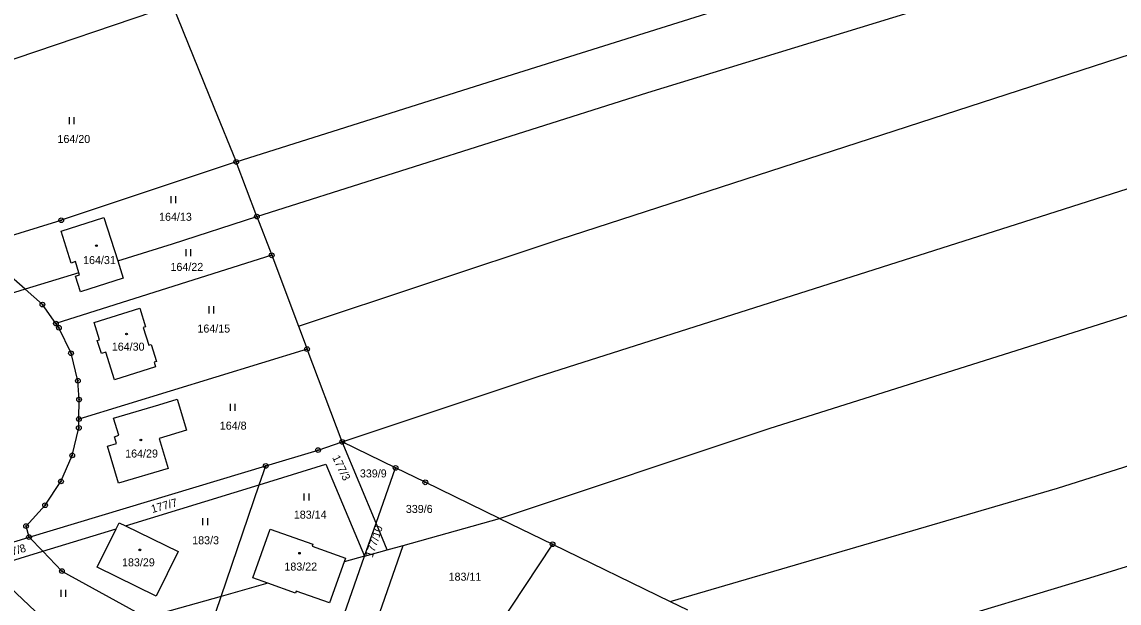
# Model space of a CAD drawing. Extents: x -762263 to -760336, y -1154405 to -1152076.
# Drawn here: x -761336.3 to -761103.3, y -1152463.4 to -1152340 of the extents above; entities that cross this region are included whole.
import ezdxf

# ---------------------------------------------------------------- set-up
doc = ezdxf.new("R2010")
doc.units = 0
for name, color, linetype in [('Vrstva 1', 7, 'Continuous'), ('Vrstva 18', 7, 'Continuous'), ('Vrstva 19', 7, 'Continuous'), ('Vrstva 24', 7, 'Continuous'), ('Vrstva 25', 7, 'Continuous'), ('Vrstva 6', 7, 'Continuous')]:
    doc.layers.add(name, color=color, linetype=linetype)

msp = doc.modelspace()

# ---------------------------------------------------------------- linework, layer by layer
at = {"layer": 'Vrstva 1'}
for p, q in [((-761375.09, -1152360.47), (-761304.35, -1152336.41)), ((-761304.35, -1152336.41), (-761295.51, -1152358.08)), ((-761295.51, -1152358.08), (-761290.77, -1152369.71)), ((-761290.77, -1152369.71), (-761327.94, -1152382.1)), ((-761286.38, -1152381.32), (-761290.77, -1152369.71)), ((-761348.02, -1152388.29), (-761327.94, -1152382.1)), ((-761327.95, -1152384.4), (-761318.87, -1152381.51)), ((-761318.87, -1152381.51), (-761315.96, -1152390.72)), ((-761304.29, -1152387.14), (-761286.38, -1152381.32)), ((-761286.38, -1152381.32), (-761283.26, -1152389.55)), ((-761325.83, -1152391.19), (-761327.95, -1152384.4)), ((-761315.96, -1152390.72), (-761304.29, -1152387.14)), ((-761283.26, -1152389.55), (-761329.07, -1152404.03)), ((-761324.89, -1152390.89), (-761325.83, -1152391.19)), ((-761324.18, -1152393.25), (-761324.89, -1152390.89)), ((-761315.96, -1152390.72), (-761314.79, -1152394.42)), ((-761283.26, -1152389.55), (-761277.56, -1152404.6)), ((-761335.62, -1152396.76), (-761339.78, -1152393.07)), ((-761324.18, -1152393.25), (-761335.62, -1152396.76)), ((-761324.94, -1152394), (-761324.04, -1152393.72)), ((-761324.04, -1152393.72), (-761324.18, -1152393.25)), ((-761323.88, -1152397.3), (-761324.94, -1152394)), ((-761314.79, -1152394.42), (-761323.88, -1152397.3)), ((-761335.62, -1152396.76), (-761370.71, -1152407.53)), ((-761331.94, -1152400.01), (-761335.62, -1152396.76)), ((-761329.07, -1152404.03), (-761331.94, -1152400.01)), ((-761320.98, -1152403.83), (-761311.29, -1152400.78)), ((-761311.29, -1152400.78), (-761310.05, -1152404.74)), ((-761328.44, -1152404.92), (-761329.07, -1152404.03)), ((-761325.87, -1152410.35), (-761328.44, -1152404.92)), ((-761319.81, -1152407.5), (-761320.98, -1152403.83)), ((-761310.05, -1152404.74), (-761310.52, -1152404.89)), ((-761310.52, -1152404.89), (-761309.33, -1152408.66)), ((-761277.56, -1152404.6), (-761275.73, -1152409.45)), ((-761320.29, -1152407.65), (-761319.81, -1152407.5)), ((-761319.41, -1152410.41), (-761320.29, -1152407.65)), ((-761275.73, -1152409.45), (-761324.2, -1152424.32)), ((-761318.45, -1152410.1), (-761319.41, -1152410.41)), ((-761316.61, -1152415.97), (-761318.45, -1152410.1)), ((-761309.33, -1152408.66), (-761308.86, -1152408.51)), ((-761308.86, -1152408.51), (-761307.73, -1152412.1)), ((-761268.27, -1152429.17), (-761275.73, -1152409.45)), ((-761324.42, -1152416.19), (-761325.87, -1152410.35)), ((-761307.73, -1152412.1), (-761308.2, -1152412.25)), ((-761308.2, -1152412.25), (-761307.9, -1152413.23)), ((-761307.9, -1152413.23), (-761316.61, -1152415.97)), ((-761324.17, -1152420.19), (-761324.42, -1152416.19)), ((-761324.2, -1152424.32), (-761324.17, -1152420.19)), ((-761316.82, -1152424.13), (-761307.2, -1152421.27)), ((-761307.2, -1152421.27), (-761303.31, -1152420.06)), ((-761303.31, -1152420.06), (-761301.32, -1152426.7)), ((-761315.71, -1152427.77), (-761316.82, -1152424.13)), ((-761325.6, -1152432.03), (-761324.21, -1152426.19)), ((-761324.21, -1152426.19), (-761324.2, -1152424.32)), ((-761316.67, -1152428.06), (-761315.71, -1152427.77)), ((-761316.23, -1152429.53), (-761316.67, -1152428.06)), ((-761301.32, -1152426.7), (-761307.14, -1152428.45)), ((-761307.14, -1152428.45), (-761305.26, -1152434.78)), ((-761318.15, -1152430.1), (-761316.23, -1152429.53)), ((-761315.8, -1152437.92), (-761318.15, -1152430.1)), ((-761284.52, -1152434.27), (-761273.41, -1152430.92)), ((-761273.41, -1152430.92), (-761268.27, -1152429.17)), ((-761256.95, -1152434.68), (-761268.27, -1152429.17)), ((-761261.08, -1152446.42), (-761268.27, -1152429.17)), ((-761328, -1152437.55), (-761325.6, -1152432.03)), ((-761334.79, -1152449.39), (-761284.52, -1152434.27)), ((-761305.26, -1152434.78), (-761315.8, -1152437.92)), ((-761285.88, -1152438.25), (-761271.79, -1152433.92)), ((-761285.88, -1152438.25), (-761284.52, -1152434.27)), ((-761271.79, -1152433.92), (-761263.54, -1152453.43)), ((-761261.08, -1152446.42), (-761256.95, -1152434.68)), ((-761250.63, -1152437.75), (-761256.95, -1152434.68)), ((-761331.37, -1152442.61), (-761328, -1152437.55)), ((-761234.91, -1152445.4), (-761250.63, -1152437.75)), ((-761314.29, -1152446.98), (-761285.88, -1152438.25)), ((-761293.98, -1152461.97), (-761285.88, -1152438.25)), ((-761335.42, -1152447.04), (-761331.37, -1152442.61)), ((-761334.79, -1152449.39), (-761335.42, -1152447.04)), ((-761316.25, -1152447.59), (-761315.63, -1152446.33)), ((-761315.63, -1152446.33), (-761314.29, -1152446.98)), ((-761314.29, -1152446.98), (-761303.1, -1152452.47)), ((-761263.54, -1152453.43), (-761261.08, -1152446.42)), ((-761258.72, -1152452.08), (-761261.08, -1152446.42)), ((-761255.32, -1152451.13), (-761234.91, -1152445.4)), ((-761234.91, -1152445.4), (-761223.61, -1152450.9)), ((-761346.42, -1152452.92), (-761334.79, -1152449.39)), ((-761331.87, -1152452.39), (-761334.79, -1152449.39)), ((-761331.87, -1152452.39), (-761316.25, -1152447.59)), ((-761320.33, -1152455.78), (-761316.25, -1152447.59)), ((-761287.27, -1152458.04), (-761283.58, -1152447.67)), ((-761283.58, -1152447.67), (-761274.54, -1152450.89)), ((-761274.54, -1152450.89), (-761274.69, -1152451.31)), ((-761274.69, -1152451.31), (-761267.58, -1152453.84)), ((-761265.65, -1152480.62), (-761255.32, -1152451.13)), ((-761263.54, -1152453.43), (-761258.72, -1152452.08)), ((-761258.72, -1152452.08), (-761255.32, -1152451.13)), ((-761223.61, -1152450.9), (-761248.59, -1152488.42)), ((-761223.61, -1152450.9), (-761198.63, -1152463.05)), ((-761343.27, -1152455.9), (-761331.87, -1152452.39)), ((-761331.87, -1152452.39), (-761327.79, -1152456.59)), ((-761303.1, -1152452.47), (-761307.8, -1152461.9)), ((-761272.42, -1152478.69), (-761263.54, -1152453.43)), ((-761263.54, -1152453.43), (-761267.87, -1152454.64)), ((-761267.58, -1152453.84), (-761267.87, -1152454.64)), ((-761343.27, -1152455.9), (-761333.49, -1152465.14)), ((-761327.79, -1152456.59), (-761309.91, -1152466.44)), ((-761307.8, -1152461.9), (-761320.33, -1152455.78)), ((-761267.87, -1152454.64), (-761270.96, -1152463.35)), ((-761284.05, -1152459.18), (-761287.27, -1152458.04)), ((-761284.05, -1152459.18), (-761293.98, -1152461.97)), ((-761278.22, -1152461.25), (-761284.05, -1152459.18)), ((-761278.06, -1152460.83), (-761278.22, -1152461.25)), ((-761270.96, -1152463.35), (-761278.06, -1152460.83)), ((-761293.98, -1152461.97), (-761309.91, -1152466.44)), ((-761297.08, -1152471.04), (-761293.98, -1152461.97)), ((-761198.63, -1152463.05), (-761194.96, -1152464.84))]:
    msp.add_line(p, q, dxfattribs=at)
at = {"layer": 'Vrstva 24'}
for centre, radius in [((-761290.77, -1152369.71), 0.5), ((-761290.77, -1152369.71), 0.1), ((-761327.94, -1152382.1), 0.5), ((-761327.94, -1152382.1), 0.1), ((-761286.38, -1152381.32), 0.5), ((-761286.38, -1152381.32), 0.1), ((-761283.26, -1152389.55), 0.5), ((-761283.26, -1152389.55), 0.1), ((-761331.94, -1152400.01), 0.5), ((-761331.94, -1152400.01), 0.1), ((-761329.07, -1152404.03), 0.5), ((-761329.07, -1152404.03), 0.1), ((-761328.44, -1152404.92), 0.5), ((-761328.44, -1152404.92), 0.1), ((-761325.87, -1152410.35), 0.5), ((-761275.73, -1152409.45), 0.5), ((-761275.73, -1152409.45), 0.1), ((-761325.87, -1152410.35), 0.1), ((-761324.42, -1152416.19), 0.5), ((-761324.42, -1152416.19), 0.1), ((-761324.17, -1152420.19), 0.5), ((-761324.17, -1152420.19), 0.1), ((-761324.2, -1152424.32), 0.5), ((-761324.21, -1152426.19), 0.5), ((-761324.21, -1152426.19), 0.1), ((-761324.2, -1152424.32), 0.1), ((-761268.27, -1152429.17), 0.5), ((-761273.41, -1152430.92), 0.5), ((-761273.41, -1152430.92), 0.1), ((-761268.27, -1152429.17), 0.1), ((-761325.6, -1152432.03), 0.5), ((-761325.6, -1152432.03), 0.1), ((-761284.52, -1152434.27), 0.5), ((-761284.52, -1152434.27), 0.1), ((-761256.95, -1152434.68), 0.5), ((-761256.95, -1152434.68), 0.1), ((-761328, -1152437.55), 0.5), ((-761328, -1152437.55), 0.1), ((-761250.63, -1152437.75), 0.5), ((-761250.63, -1152437.75), 0.1), ((-761331.37, -1152442.61), 0.5), ((-761331.37, -1152442.61), 0.1), ((-761335.42, -1152447.04), 0.5), ((-761335.42, -1152447.04), 0.1), ((-761334.79, -1152449.39), 0.5), ((-761334.79, -1152449.39), 0.1), ((-761223.61, -1152450.9), 0.5), ((-761223.61, -1152450.9), 0.1), ((-761327.79, -1152456.59), 0.5), ((-761327.79, -1152456.59), 0.1)]:
    msp.add_circle(centre, radius, dxfattribs=at)
at = {"layer": 'Vrstva 25'}
for p, q in [((-761326.2, -1152361.71), (-761326.2, -1152360.21)), ((-761325.2, -1152361.71), (-761325.2, -1152360.21)), ((-761304.58, -1152378.5), (-761304.58, -1152377)), ((-761303.58, -1152378.5), (-761303.58, -1152377)), ((-761301.41, -1152389.71), (-761301.41, -1152388.21)), ((-761300.41, -1152389.71), (-761300.41, -1152388.21)), ((-761296.56, -1152401.87), (-761296.56, -1152400.37)), ((-761295.56, -1152401.87), (-761295.56, -1152400.37)), ((-761292, -1152422.57), (-761292, -1152421.07)), ((-761291, -1152422.57), (-761291, -1152421.07)), ((-761276.33, -1152441.61), (-761276.33, -1152440.11)), ((-761275.33, -1152441.61), (-761275.33, -1152440.11)), ((-761297.85, -1152446.85), (-761297.85, -1152445.35)), ((-761296.85, -1152446.85), (-761296.85, -1152445.35)), ((-761327.98, -1152462.08), (-761327.98, -1152460.58)), ((-761326.98, -1152462.08), (-761326.98, -1152460.58))]:
    msp.add_line(p, q, dxfattribs=at)
for centre in [(-761320.47, -1152387.5), (-761314.08, -1152406.26), (-761311.04, -1152428.75), (-761311.25, -1152452.1), (-761277.35, -1152452.8)]:
    msp.add_circle(centre, 0.175, dxfattribs=at)
at = {"layer": 'Vrstva 6'}
for p, q in [((-761233.23, -1152351.5), (-761158.78, -1152328.09)), ((-761203.4, -1152354.97), (-761131.77, -1152333.02)), ((-761222.2, -1152386.19), (-761080.99, -1152340.36)), ((-761290.77, -1152369.71), (-761233.23, -1152351.5)), ((-761125.07, -1152382.93), (-761023.79, -1152350.66)), ((-761286.38, -1152381.32), (-761203.4, -1152354.97)), ((-761177.6, -1152426.33), (-761011.21, -1152373.77)), ((-761226.69, -1152415.3), (-761125.07, -1152382.93)), ((-761277.56, -1152404.6), (-761222.2, -1152386.19)), ((-761268.27, -1152429.17), (-761226.69, -1152415.3)), ((-761116.41, -1152439.01), (-761041.45, -1152415.1)), ((-761234.91, -1152445.4), (-761177.6, -1152426.33)), ((-761109.5, -1152458.03), (-761028.52, -1152432.79)), ((-761198.63, -1152463.05), (-761116.41, -1152439.01)), ((-761158.57, -1152472.79), (-761109.5, -1152458.03))]:
    msp.add_line(p, q, dxfattribs=at)

# ---------------------------------------------------------------- texts
at = {"layer": 'Vrstva 18'}
for s, p in [('164/20', (-761328.747, -1152365.69)), ('164/13', (-761307.167, -1152382.22)), ('164/22', (-761304.747, -1152392.86)), ('164/15', (-761299.027, -1152405.95)), ('164/8', (-761294.277, -1152426.56)), ('339/9', (-761264.523, -1152436.71)), ('339/6', (-761254.763, -1152444.25)), ('183/14', (-761278.557, -1152445.46)), ('183/3', (-761300.137, -1152450.9)), ('183/11', (-761245.687, -1152458.64))]:
    msp.add_text(s, height=1.7, dxfattribs=at).set_placement(p)
for s, rotation, p in [('177/3', 295.70352, (-761270.45, -1152432.454)), ('177/7', 15.58445, (-761308.612, -1152444.284)), ('177/10', 71.56243, (-761261.827, -1152453.86)), ('177/8', 16.50118, (-761340.743, -1152454.028))]:
    msp.add_text(s, height=1.7, rotation=rotation, dxfattribs=at).set_placement(p)
at = {"layer": 'Vrstva 19'}
for s, p in [('164/31', (-761323.307, -1152391.41)), ('164/30', (-761317.207, -1152409.79)), ('164/29', (-761314.367, -1152432.48)), ('183/29', (-761315.037, -1152455.59)), ('183/22', (-761280.557, -1152456.49))]:
    msp.add_text(s, height=1.7, dxfattribs=at).set_placement(p)

doc.saveas('drawing.dxf')
